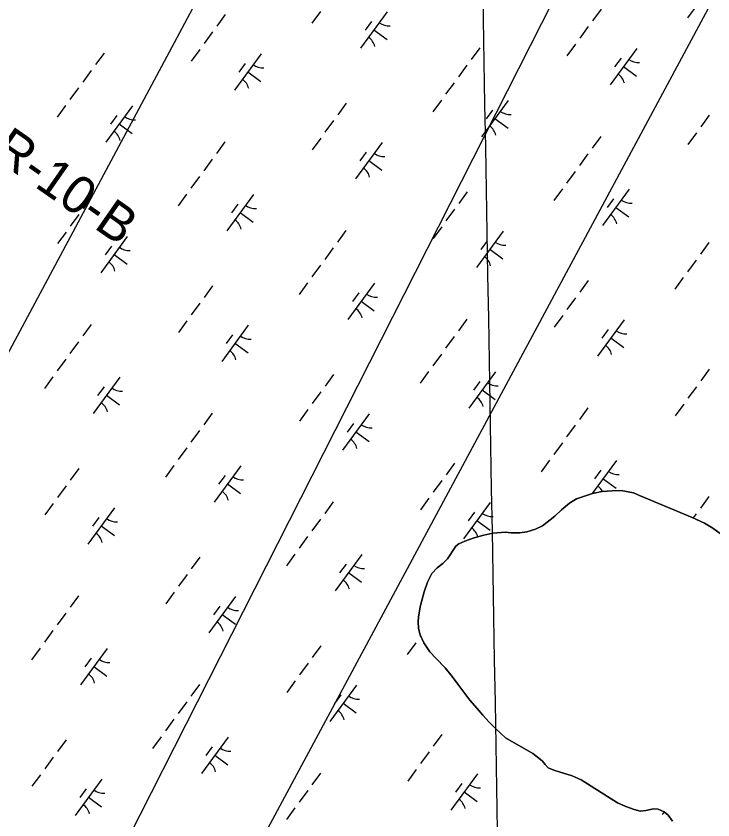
# Model space of a CAD drawing. Extents: x 3905714 to 3926767, y 183354 to 205755.
# Drawn here: x 3919561 to 3920334, y 194107 to 194998 of the extents above; entities that cross this region are included whole.
import ezdxf

# ---------------------------------------------------------------- set-up
doc = ezdxf.new("R2010")
doc.units = 0
for name, color, linetype in [('V-GRID-MAJR', 7, 'Continuous'), ('V-RIVR-RANG-IDEN', 7, 'Continuous'), ('V-TOPO-SHOR', 7, 'Continuous'), ('V-UTIL-LINE', 7, 'Continuous'), ('V-WETL-SWMP', 7, 'Continuous')]:
    doc.layers.add(name, color=color, linetype=linetype)

msp = doc.modelspace()

# ---------------------------------------------------------------- linework, layer by layer
at = {"layer": 'V-GRID-MAJR'}
msp.add_spline([(3920162.98, 190214.61), (3920105.98, 193480.1), (3920000.19, 199540.18), (3919966.26, 201484.22)], degree=3, dxfattribs=at)
at = {"layer": 'V-TOPO-SHOR'}
for points in [[(3920259.75, 194118), (3920253.51, 194117.05), (3920246.5, 194118.83), (3920237.54, 194122.17), (3920228.01, 194126.49), (3920187.75, 194151.78), (3920177.83, 194156.3), (3920172.18, 194158.27), (3920164.59, 194160.44), (3920157.58, 194162.42), (3920151.15, 194165.17), (3920147.85, 194168.69), (3920144.94, 194172.4), (3920140.86, 194175.73), (3920134.25, 194181.21), (3920104.1, 194198.48), (3920092.83, 194208.65), (3920085.84, 194215.89), (3920078.85, 194223.52), (3920072.45, 194230.95), (3920064.29, 194240.14), (3920051.1, 194257.93), (3920044.9, 194266.52), (3920036.94, 194275.91), (3920026.65, 194286.67), (3920020.04, 194293.9), (3920013.26, 194303.67), (3920009.2, 194312.65), (3920007.66, 194319.48), (3920007.1, 194327.28), (3920007.51, 194332.15), (3920009.31, 194343.65), (3920013.66, 194360.39), (3920017.4, 194371.1), (3920022.3, 194380.44), (3920028.18, 194386.66), (3920034.62, 194391.51), (3920039.71, 194396.75), (3920048.73, 194410.75), (3920052.25, 194413.47), (3920058.89, 194416.37), (3920069.23, 194420.03), (3920079.77, 194423.12), (3920090.1, 194425.22), (3920103.56, 194426.34), (3920110.38, 194425.74), (3920119.73, 194425.51), (3920127.73, 194426.84), (3920137.1, 194429.73), (3920145.1, 194433.21), (3920158.59, 194444.08), (3920166.22, 194451.26), (3920174.82, 194458.44), (3920182.63, 194463.29), (3920192.59, 194466.76), (3920200.59, 194469.27), (3920211.12, 194471.57), (3920222.24, 194472.31), (3920232.18, 194472.66), (3920245.81, 194469.89), (3920252.43, 194467.13), (3920310.82, 194442.75), (3920324.83, 194436.27), (3920333.78, 194430.98), (3920343.5, 194423.92)], [(3920289.14, 194106.2), (3920284.49, 194112.65), (3920279.82, 194116.56), (3920273.21, 194119.31), (3920267.94, 194119.53), (3920259.75, 194118)]]:
    msp.add_lwpolyline(points, dxfattribs=at)
at = {"layer": 'V-UTIL-LINE'}
for points in [[(3922094.67, 198742.56), (3921080.02, 197477.61), (3915734.79, 187496.67)], [(3915141.88, 186857.82), (3915602.26, 187412.44), (3917208.62, 188427.22), (3918201.85, 190592.37), (3918499.52, 191341.67), (3918705.19, 192156.56), (3920335.23, 195367.27), (3921815.24, 198099.69), (3922187.19, 198661.56)], [(3919053.82, 189827.07), (3918313.52, 190612.09), (3918520.46, 191058.29), (3918753.91, 192077.3), (3920478.53, 195285.34), (3921148.44, 196586.73), (3921587.51, 197419.94), (3921944.61, 198057.47)]]:
    msp.add_lwpolyline(points, dxfattribs=at)
at = {"layer": 'V-WETL-SWMP'}
for p, q in [((3920315.32, 195009.34), (3920305.86, 194996.43)), ((3919793.24, 195000.22), (3919783.78, 194987.31)), ((3919898.65, 195003.51), (3919889.19, 194990.6)), ((3919972.83, 195003.18), (3919943.28, 194962.85)), ((3920209.91, 195006.04), (3920200.45, 194993.14)), ((3919955.38, 194992.42), (3919948.29, 194982.74)), ((3919779.05, 194980.86), (3919769.6, 194967.95)), ((3919958.06, 194983.02), (3919972.58, 194972.38)), ((3920195.72, 194986.68), (3920186.27, 194973.78)), ((3920075.38, 194963.28), (3920065.92, 194950.38)), ((3920181.54, 194967.32), (3920172.08, 194954.42)), ((3919658.71, 194957.46), (3919649.25, 194944.55)), ((3919764.87, 194961.5), (3919755.41, 194948.59)), ((3919832.88, 194956.67), (3919803.33, 194916.33)), ((3920249.55, 194962.49), (3920220, 194922.16)), ((3919815.42, 194945.9), (3919808.33, 194936.22)), ((3920232.1, 194951.73), (3920225, 194942.05)), ((3919644.52, 194938.1), (3919635.07, 194925.19)), ((3919818.1, 194936.5), (3919832.62, 194925.86)), ((3920061.19, 194943.92), (3920051.74, 194931.02)), ((3920234.77, 194942.33), (3920249.29, 194931.69)), ((3919630.34, 194918.74), (3919620.88, 194905.83)), ((3920047.01, 194924.56), (3920037.55, 194911.66)), ((3919927.41, 194901.91), (3919917.96, 194889.01)), ((3920032.83, 194905.2), (3920023.37, 194892.3)), ((3920107.01, 194904.88), (3920077.46, 194864.54)), ((3919616.15, 194899.38), (3919606.7, 194886.47)), ((3919690.34, 194899.05), (3919660.79, 194858.72)), ((3920089.56, 194894.11), (3920082.47, 194884.43)), ((3919672.88, 194888.28), (3919665.79, 194878.6)), ((3920092.23, 194884.71), (3920106.75, 194874.07)), ((3920329.9, 194888.38), (3920320.45, 194875.47)), ((3919675.56, 194878.88), (3919690.08, 194868.25)), ((3919913.23, 194882.55), (3919903.77, 194869.65)), ((3920209.56, 194864.98), (3920200.1, 194852.07)), ((3920315.72, 194869.02), (3920306.26, 194856.11)), ((3919792.88, 194859.15), (3919783.43, 194846.25)), ((3919899.05, 194863.19), (3919889.59, 194850.29)), ((3919967.06, 194858.36), (3919937.51, 194818.03)), ((3919949.6, 194847.59), (3919942.51, 194837.91)), ((3919778.7, 194839.79), (3919769.24, 194826.89)), ((3919952.28, 194838.19), (3919966.8, 194827.56)), ((3920195.37, 194845.62), (3920185.92, 194832.71)), ((3919764.52, 194820.43), (3919755.06, 194807.53)), ((3920181.19, 194826.26), (3920171.73, 194813.35)), ((3920061.59, 194803.61), (3920052.14, 194790.7)), ((3920167.01, 194806.9), (3920157.55, 194793.99)), ((3920241.19, 194806.57), (3920211.64, 194766.24)), ((3919644.92, 194797.78), (3919635.46, 194784.87)), ((3919750.33, 194801.07), (3919740.88, 194788.17)), ((3919824.52, 194800.75), (3919794.97, 194760.41)), ((3920223.74, 194795.8), (3920216.64, 194786.12)), ((3919807.06, 194789.98), (3919799.97, 194780.3)), ((3920226.41, 194786.4), (3920240.93, 194775.77)), ((3919630.74, 194778.42), (3919621.28, 194765.51)), ((3919809.74, 194780.58), (3919824.26, 194769.94)), ((3920047.41, 194784.25), (3920037.95, 194771.34)), ((3919616.55, 194759.06), (3919607.1, 194746.15)), ((3919927.06, 194760.85), (3919917.61, 194747.94)), ((3920033.23, 194764.89), (3920023.77, 194751.98)), ((3920101.23, 194760.06), (3920071.68, 194719.72)), ((3919684.56, 194754.23), (3919655.01, 194713.9)), ((3920083.78, 194749.29), (3920076.69, 194739.61)), ((3919667.11, 194743.46), (3919660.02, 194733.78)), ((3919912.88, 194741.49), (3919903.42, 194728.58)), ((3920329.55, 194747.31), (3920320.1, 194734.41)), ((3919669.79, 194734.06), (3919684.31, 194723.43)), ((3920086.46, 194739.89), (3920100.98, 194729.25)), ((3920315.37, 194727.95), (3920305.91, 194715.05)), ((3919898.7, 194722.13), (3919889.24, 194709.22)), ((3920195.77, 194705.3), (3920186.32, 194692.39)), ((3920301.19, 194708.59), (3920291.73, 194695.69)), ((3919779.1, 194699.48), (3919769.64, 194686.57)), ((3919884.51, 194702.77), (3919875.06, 194689.86)), ((3919958.7, 194702.44), (3919929.15, 194662.11)), ((3919941.24, 194691.67), (3919934.15, 194681.99)), ((3919764.92, 194680.12), (3919755.46, 194667.21)), ((3919943.92, 194682.27), (3919958.44, 194671.63)), ((3920181.59, 194685.94), (3920172.13, 194673.03)), ((3919750.73, 194660.76), (3919741.28, 194647.85)), ((3920061.24, 194662.54), (3920051.79, 194649.64)), ((3920167.41, 194666.58), (3920157.95, 194653.67)), ((3920235.41, 194661.75), (3920205.86, 194621.42)), ((3919644.57, 194656.72), (3919635.11, 194643.81)), ((3919818.74, 194655.92), (3919789.19, 194615.59)), ((3920217.96, 194650.98), (3920210.87, 194641.3)), ((3919801.29, 194645.16), (3919794.2, 194635.48)), ((3920047.06, 194643.18), (3920037.6, 194630.27)), ((3919630.39, 194637.36), (3919620.93, 194624.45)), ((3919803.97, 194635.76), (3919818.49, 194625.12)), ((3920220.64, 194641.58), (3920235.16, 194630.94)), ((3919616.2, 194618), (3919606.75, 194605.09)), ((3920032.88, 194623.82), (3920023.42, 194610.91)), ((3920329.95, 194606.99), (3920320.5, 194594.09)), ((3919602.02, 194598.64), (3919592.56, 194585.73)), ((3919676.2, 194598.31), (3919646.65, 194557.97)), ((3919913.28, 194601.17), (3919903.82, 194588.26)), ((3920018.69, 194604.46), (3920009.24, 194591.55)), ((3920092.87, 194604.13), (3920063.32, 194563.8)), ((3920075.42, 194593.37), (3920068.33, 194583.69)), ((3919658.75, 194587.54), (3919651.66, 194577.86)), ((3919899.1, 194581.81), (3919889.64, 194568.9)), ((3920078.1, 194583.97), (3920092.62, 194573.33)), ((3920315.77, 194587.63), (3920306.31, 194574.73)), ((3919661.43, 194578.14), (3919675.95, 194567.5)), ((3919884.91, 194562.45), (3919875.46, 194549.54)), ((3920195.42, 194564.24), (3920185.97, 194551.33)), ((3920301.58, 194568.27), (3920292.13, 194555.37)), ((3919778.75, 194558.41), (3919769.29, 194545.5)), ((3919952.92, 194557.62), (3919923.37, 194517.28)), ((3919935.47, 194546.85), (3919928.38, 194537.17)), ((3920181.24, 194544.88), (3920171.78, 194531.97)), ((3919764.57, 194539.05), (3919755.11, 194526.14)), ((3919938.15, 194537.45), (3919952.67, 194526.81)), ((3919750.38, 194519.69), (3919740.93, 194506.78)), ((3920167.05, 194525.52), (3920157.6, 194512.61)), ((3919736.2, 194500.33), (3919726.74, 194487.42)), ((3919810.38, 194500), (3919780.83, 194459.67)), ((3920047.46, 194502.86), (3920038, 194489.96)), ((3920152.87, 194506.16), (3920143.41, 194493.25)), ((3920227.05, 194505.83), (3920200.17, 194469.14)), ((3919630.79, 194497.04), (3919621.33, 194484.13)), ((3920209.6, 194495.06), (3920202.51, 194485.38)), ((3919792.93, 194489.24), (3919785.84, 194479.56)), ((3920033.27, 194483.5), (3920023.82, 194470.6)), ((3920212.28, 194485.66), (3920226.8, 194475.02)), ((3919616.6, 194477.68), (3919607.15, 194464.77)), ((3919795.61, 194479.84), (3919810.13, 194469.2)), ((3920019.09, 194464.14), (3920009.63, 194451.24)), ((3920192.59, 194466.76), (3920182.64, 194463.29)), ((3920200.59, 194469.27), (3920192.59, 194466.76)), ((3920211.12, 194471.57), (3920200.59, 194469.27)), ((3920222.24, 194472.31), (3920211.12, 194471.57)), ((3920232.18, 194472.66), (3920222.24, 194472.31)), ((3920245.81, 194469.89), (3920232.18, 194472.66)), ((3920252.43, 194467.13), (3920245.81, 194469.89)), ((3920310.82, 194442.75), (3920252.43, 194467.13)), ((3920329.6, 194465.93), (3920320.15, 194453.02)), ((3919602.42, 194458.32), (3919592.96, 194445.41)), ((3919912.93, 194460.1), (3919903.47, 194447.2)), ((3920087.1, 194459.31), (3920057.55, 194418.98)), ((3920174.82, 194458.44), (3920166.22, 194451.26)), ((3920182.64, 194463.29), (3920174.82, 194458.44)), ((3919670.43, 194453.49), (3919640.88, 194413.15)), ((3920069.65, 194448.55), (3920062.55, 194438.87)), ((3920166.22, 194451.26), (3920158.59, 194444.08)), ((3920315.42, 194446.57), (3920312.17, 194442.13)), ((3919652.97, 194442.72), (3919645.88, 194433.04)), ((3919898.74, 194440.74), (3919889.29, 194427.84)), ((3920072.32, 194439.15), (3920086.84, 194428.51)), ((3920158.59, 194444.08), (3920145.1, 194433.21)), ((3920324.83, 194436.27), (3920310.82, 194442.75)), ((3919655.65, 194433.32), (3919670.17, 194422.68)), ((3920137.1, 194429.73), (3920127.73, 194426.84)), ((3920145.1, 194433.21), (3920137.1, 194429.73)), ((3920333.78, 194430.97), (3920324.83, 194436.27)), ((3920343.5, 194423.92), (3920333.78, 194430.97)), ((3919884.56, 194421.38), (3919875.1, 194408.48)), ((3920069.23, 194420.04), (3920058.89, 194416.37)), ((3920079.77, 194423.12), (3920069.23, 194420.04)), ((3920090.1, 194425.22), (3920079.77, 194423.12)), ((3920103.56, 194426.34), (3920090.1, 194425.22)), ((3920110.38, 194425.73), (3920103.56, 194426.34)), ((3920119.73, 194425.51), (3920110.38, 194425.73)), ((3920127.73, 194426.84), (3920119.73, 194425.51)), ((3920048.73, 194410.75), (3920039.71, 194396.75)), ((3920052.25, 194413.47), (3920048.73, 194410.75)), ((3920058.89, 194416.37), (3920052.25, 194413.47)), ((3919870.38, 194402.02), (3919860.92, 194389.12)), ((3919944.56, 194401.7), (3919915.01, 194361.36)), ((3919764.97, 194398.73), (3919755.51, 194385.83)), ((3920039.71, 194396.75), (3920034.62, 194391.51)), ((3919927.11, 194390.93), (3919920.02, 194381.25)), ((3920028.18, 194386.66), (3920022.31, 194380.44)), ((3920034.62, 194391.51), (3920028.18, 194386.66)), ((3919750.78, 194379.37), (3919741.33, 194366.47)), ((3919929.79, 194381.53), (3919944.31, 194370.89)), ((3920022.31, 194380.44), (3920017.4, 194371.1)), ((3920017.4, 194371.1), (3920013.66, 194360.39)), ((3919736.6, 194360.01), (3919727.14, 194347.11)), ((3920013.66, 194360.39), (3920009.31, 194343.65)), ((3919630.44, 194355.97), (3919620.98, 194343.07)), ((3919804.61, 194355.18), (3919775.06, 194314.85)), ((3919787.15, 194344.41), (3919780.06, 194334.73)), ((3920009.31, 194343.65), (3920007.51, 194332.15)), ((3919616.25, 194336.61), (3919606.8, 194323.71)), ((3919789.83, 194335.01), (3919804.35, 194324.38)), ((3920007.51, 194332.15), (3920007.1, 194327.28)), ((3920007.1, 194327.28), (3920007.66, 194319.48)), ((3919602.07, 194317.25), (3919592.61, 194304.35)), ((3920007.66, 194319.48), (3920009.2, 194312.65)), ((3920009.2, 194312.65), (3920013.26, 194303.67)), ((3920004.56, 194303.72), (3919995.1, 194290.81)), ((3920009.92, 194311.04), (3920009.28, 194310.17)), ((3920013.26, 194303.67), (3920020.04, 194293.9)), ((3919587.88, 194297.89), (3919578.43, 194284.99)), ((3919662.07, 194297.57), (3919632.52, 194257.23)), ((3919899.14, 194300.43), (3919889.69, 194287.52)), ((3919644.61, 194286.8), (3919637.52, 194277.12)), ((3920020.04, 194293.9), (3920026.65, 194286.67)), ((3920026.65, 194286.67), (3920036.94, 194275.91)), ((3919647.29, 194277.4), (3919661.81, 194266.76)), ((3919884.96, 194281.07), (3919875.5, 194268.16)), ((3920036.94, 194275.91), (3920044.9, 194266.52)), ((3919870.78, 194261.71), (3919861.32, 194248.8)), ((3920044.9, 194266.52), (3920051.1, 194257.92)), ((3919764.61, 194257.67), (3919755.16, 194244.76)), ((3919938.79, 194256.88), (3919909.24, 194216.54)), ((3920051.1, 194257.92), (3920064.29, 194240.14)), ((3919921.33, 194246.11), (3919914.24, 194236.43)), ((3919750.43, 194238.31), (3919740.97, 194225.4)), ((3919924.01, 194236.71), (3919938.53, 194226.07)), ((3920064.29, 194240.14), (3920072.45, 194230.95)), ((3920072.45, 194230.95), (3920078.85, 194223.52)), ((3920078.85, 194223.52), (3920085.84, 194215.89)), ((3919736.25, 194218.95), (3919726.79, 194206.04)), ((3920085.84, 194215.89), (3920092.83, 194208.65)), ((3920092.83, 194208.65), (3920104.1, 194198.48)), ((3919722.06, 194199.59), (3919712.61, 194186.68)), ((3919796.25, 194199.26), (3919766.7, 194158.93)), ((3920033.32, 194202.12), (3920023.87, 194189.21)), ((3920104.1, 194198.48), (3920134.25, 194181.21)), ((3919616.65, 194196.3), (3919607.19, 194183.39)), ((3919778.79, 194188.49), (3919771.7, 194178.81)), ((3919781.47, 194179.09), (3919795.99, 194168.45)), ((3920019.14, 194182.76), (3920009.68, 194169.85)), ((3920134.25, 194181.21), (3920140.86, 194175.73)), ((3919602.47, 194176.94), (3919593.01, 194164.03)), ((3920140.86, 194175.73), (3920144.94, 194172.4)), ((3920144.94, 194172.4), (3920147.85, 194168.69)), ((3920004.96, 194163.4), (3919995.5, 194150.49)), ((3920147.85, 194168.69), (3920151.16, 194165.17)), ((3920151.16, 194165.17), (3920157.58, 194162.42)), ((3920157.58, 194162.42), (3920164.59, 194160.44)), ((3919588.28, 194157.58), (3919578.83, 194144.67)), ((3919656.29, 194152.74), (3919626.74, 194112.41)), ((3919898.79, 194159.36), (3919889.34, 194146.46)), ((3920072.96, 194158.57), (3920043.41, 194118.24)), ((3920164.59, 194160.44), (3920172.18, 194158.27)), ((3920172.18, 194158.27), (3920177.83, 194156.3)), ((3920177.83, 194156.3), (3920187.75, 194151.78)), ((3920055.51, 194147.8), (3920048.42, 194138.12)), ((3920187.75, 194151.78), (3920228.01, 194126.49)), ((3919638.84, 194141.98), (3919631.75, 194132.3)), ((3919884.61, 194140), (3919875.15, 194127.1)), ((3920058.19, 194138.4), (3920072.71, 194127.76)), ((3919641.52, 194132.58), (3919656.04, 194121.94)), ((3920228.01, 194126.49), (3920237.55, 194122.17)), ((3919870.43, 194120.64), (3919860.97, 194107.74)), ((3920237.55, 194122.17), (3920246.5, 194118.83)), ((3920246.5, 194118.83), (3920253.51, 194117.05)), ((3920253.51, 194117.05), (3920259.75, 194118)), ((3920259.75, 194118), (3920267.94, 194119.53)), ((3920267.94, 194119.53), (3920273.21, 194119.31)), ((3920273.21, 194119.31), (3920279.82, 194116.56)), ((3920279.83, 194116.55), (3920277.64, 194113.56)), ((3920279.82, 194116.56), (3920284.49, 194112.65)), ((3920284.49, 194112.65), (3920289.14, 194106.2))]:
    msp.add_line(p, q, dxfattribs=at)
for centre, start, end in [((3919974.57, 195005.16), 232.99998, 274.54364), ((3919941.92, 194960.59), 12.99998, 54.54364), ((3920251.29, 194964.47), 232.99998, 274.54364), ((3919834.62, 194958.64), 232.99998, 274.54364), ((3919801.97, 194914.08), 12.99998, 54.54364), ((3920218.64, 194919.9), 12.99998, 54.54364), ((3920108.75, 194906.85), 232.99998, 274.54364), ((3919692.08, 194901.03), 232.99998, 274.54364), ((3920076.1, 194862.29), 12.99998, 54.54364), ((3919659.43, 194856.46), 12.99998, 54.54364), ((3919968.8, 194860.34), 232.99998, 274.54364), ((3919936.15, 194815.77), 12.99998, 54.54364), ((3920242.93, 194808.54), 232.99998, 274.54364), ((3919826.26, 194802.72), 232.99998, 274.54364), ((3920210.28, 194763.98), 12.99998, 54.54364), ((3919793.61, 194758.16), 12.99998, 54.54364), ((3919686.3, 194756.2), 232.99998, 274.54364), ((3920102.98, 194762.03), 232.99998, 274.54364), ((3920070.33, 194717.47), 12.99998, 54.54364), ((3919653.65, 194711.64), 12.99998, 54.54364), ((3919960.44, 194704.41), 232.99998, 274.54364), ((3919927.79, 194659.85), 12.99998, 54.54364), ((3919820.48, 194657.9), 232.99998, 274.54364), ((3920237.15, 194663.72), 232.99998, 274.54364), ((3920204.51, 194619.16), 12.99998, 54.54364), ((3919787.83, 194613.34), 12.99998, 54.54364), ((3920094.62, 194606.11), 232.99998, 274.54364), ((3919677.94, 194600.28), 232.99998, 274.54364), ((3920061.97, 194561.55), 12.99998, 54.54364), ((3919645.29, 194555.72), 12.99998, 54.54364), ((3919954.66, 194559.59), 232.99998, 274.54364), ((3919922.01, 194515.03), 12.99998, 54.54364), ((3920228.8, 194507.8), 232.99998, 274.54364), ((3919812.12, 194501.98), 232.99998, 274.54364), ((3920196.15, 194463.24), 28.33876, 54.54364), ((3919779.47, 194457.41), 12.99998, 54.54364), ((3920088.84, 194461.29), 232.99998, 274.54364), ((3919672.17, 194455.46), 232.99998, 274.54364), ((3920056.19, 194416.72), 14.73545, 54.54364), ((3919639.52, 194410.9), 12.99998, 54.54364), ((3919946.3, 194403.67), 232.99998, 274.54364), ((3919913.65, 194359.11), 12.99998, 54.54364), ((3919806.35, 194357.16), 232.99998, 274.54364), ((3919773.7, 194312.59), 12.99998, 54.54364), ((3919663.81, 194299.54), 232.99998, 274.54364), ((3919631.16, 194254.98), 12.99998, 54.54364), ((3919940.53, 194258.85), 232.99998, 274.54364), ((3919907.88, 194214.29), 12.99998, 54.54364), ((3919797.99, 194201.23), 232.99998, 274.54364), ((3919765.34, 194156.67), 12.99998, 54.54364), ((3920074.71, 194160.54), 232.99998, 274.54364), ((3919658.03, 194154.72), 232.99998, 274.54364), ((3920042.06, 194115.98), 12.99998, 54.54364), ((3919625.38, 194110.16), 12.99998, 54.54364)]:
    msp.add_arc(centre, 17.62, start, end, dxfattribs=at)

# ---------------------------------------------------------------- texts
at = {"layer": 'V-RIVR-RANG-IDEN'}
msp.add_text('R-10-B', height=41.5, rotation=325.14435, dxfattribs=at).set_placement((3919532.47, 194843.39))

doc.saveas('drawing.dxf')
